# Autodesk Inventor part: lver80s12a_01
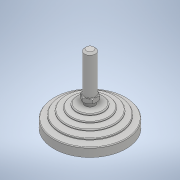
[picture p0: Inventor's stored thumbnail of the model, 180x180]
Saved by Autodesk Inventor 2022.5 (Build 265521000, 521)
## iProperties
Part Number: lver80s12a_01
Material: 一般
Document SubType Name: Modeling
Designer: ImaoCorp
Density: 1 g/cm^3
Appearance: 既定
Author: ImaoCorp
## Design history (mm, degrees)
feature "lver80s12a_01"
node "ソリッド1"
